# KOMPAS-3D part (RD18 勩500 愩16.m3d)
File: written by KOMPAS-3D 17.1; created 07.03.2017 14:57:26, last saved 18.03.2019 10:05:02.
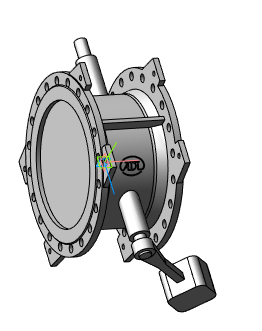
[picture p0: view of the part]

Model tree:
1. Операция без истории:2  (labels: Сталь 20  ГОСТ 1050-88)

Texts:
  RD18 Ду100 Ру16
  RD18 Ду150 Ру16
  RD18 Ду200 Ру16
  RD18 Ду250 Ру16
  RD18 Ду300 Ру16
  RD18 Ду350 Ру16
  RD18 Ду400 Ру10
  RD18 Ду400 Ру16
  RD18 Ду450 Ру10
  RD18 Ду450 Ру16
  RD18 Ду500 Ру10
  RD18 Ду500 Ру16
  RD18 Ду600 Ру10
  RD18 Ду600 Ру16
  RD18 Ду700 Ру10
  RD18 Ду700 Ру16
  RD18 Ду800 Ру10
  RD18 Ду800 Ру16
  RD18 Ду900 Ру10
  RD18 Ду900 Ру16
  RD18 Ду1000 Ру10
  RD18 Ду1000 Ру16
  RD18 Ду1200 Ру16
  RD18 Ду1400 Ру16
